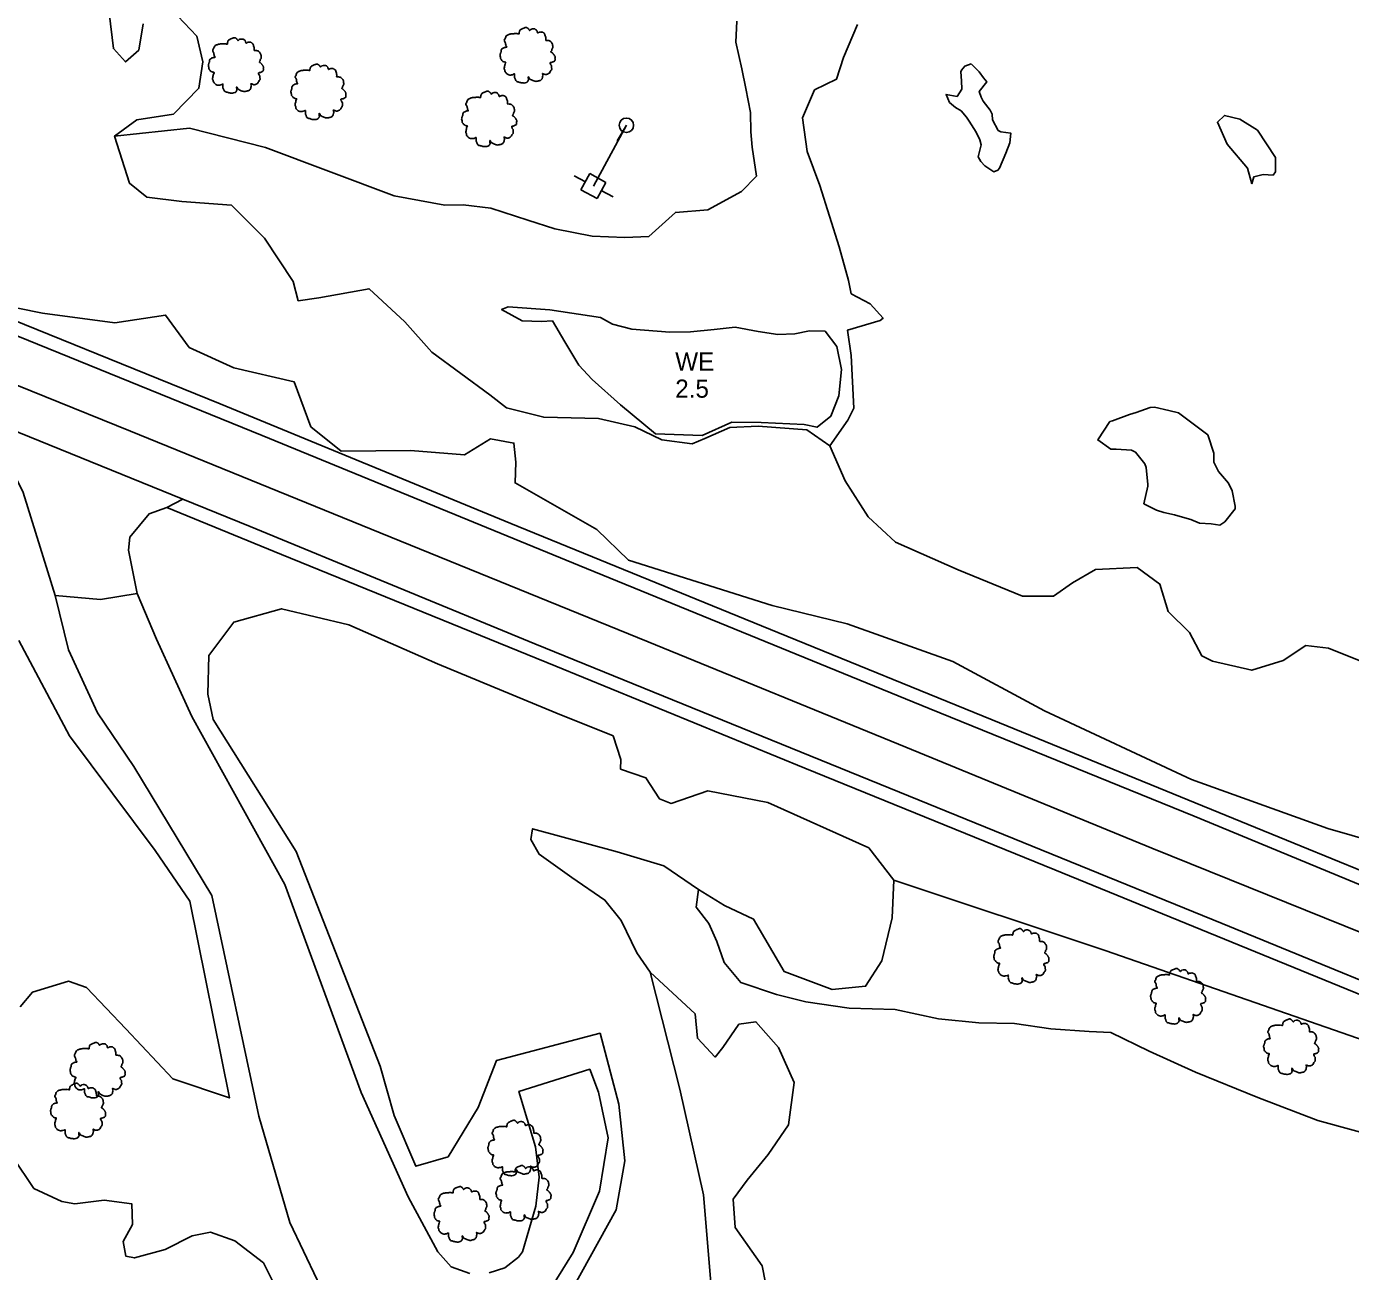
# Model space of a CAD drawing. Extents: x 2160437 to 2172832, y 205694 to 212444.
# Drawn here: x 2164307.9 to 2164673.6, y 209800.2 to 210144.2 of the extents above; entities that cross this region are included whole.
import ezdxf

# ---------------------------------------------------------------- set-up
doc = ezdxf.new("R2010")
doc.units = 0
for name, color, linetype in [('RD_EX_Driveway', 7, 'Continuous'), ('RD_EX_H2O_Pond', 7, 'Continuous'), ('RD_EX_H2O_txCode', 7, 'Continuous'), ('RD_EX_LaneStripe', 7, 'Continuous'), ('RD_EX_Road', 7, 'Continuous'), ('RD_EX_UT', 7, 'Continuous'), ('RD_EX_UT_Guy', 7, 'Continuous'), ('RD_EX_VEG', 7, 'Continuous'), ('RD_EX_VEG_ShrubLine', 7, 'Continuous'), ('RD_EX_VEG_TreeLine', 7, 'Continuous')]:
    doc.layers.add(name, color=color, linetype=linetype)

# ---------------------------------------------------------------- blocks, each defined once
blk = doc.blocks.new('T2')
at = {"layer": 'RD_EX_VEG'}
for points in [[(0.05, 7.21), (-0.25, 7.24), (-0.57, 7.14), (-0.82, 7.04), (-1.05, 6.96), (-1.27, 6.86), (-1.57, 6.69), (-1.8, 6.49), (-1.92, 6.24), (-1.97, 6.01), (-2.02, 5.74), (-2.02, 5.56), (-2.15, 5.54), (-2.3, 5.56), (-2.55, 5.64), (-2.8, 5.64), (-3.05, 5.64), (-3.4, 5.61), (-3.75, 5.61), (-4.02, 5.56), (-4.35, 5.51), (-4.72, 5.39), (-5.07, 5.26), (-5.37, 5.01), (-5.62, 4.54), (-5.75, 4.19), (-5.9, 3.94), (-5.75, 3.49), (-5.57, 3.14), (-5.55, 2.94), (-5.47, 2.52), (-5.37, 2.29), (-5.25, 2.09), (-5.32, 2.07), (-5.7, 2.02), (-6, 1.92), (-6.42, 1.69), (-6.64, 1.47), (-6.74, 1.14), (-6.77, 0.79), (-6.87, 0.59), (-6.94, 0.32), (-6.97, 0.24), (-7.02, -0.08), (-6.92, -0.53), (-6.89, -0.88), (-6.77, -1.11), (-6.62, -1.28), (-6.44, -1.53), (-6.05, -1.76), (-5.72, -1.86), (-5.52, -1.88), (-5.7, -2.38), (-5.75, -2.73), (-5.87, -3.13), (-5.87, -3.21), (-5.92, -3.68), (-5.77, -4.01), (-5.7, -4.38), (-5.52, -4.61), (-5.25, -4.91), (-4.92, -5.13), (-4.42, -5.26), (-4.02, -5.23), (-3.45, -5.06), (-3.2, -4.98), (-3.22, -5.16), (-3.2, -5.53), (-3.2, -5.96), (-3.05, -6.28), (-2.95, -6.56), (-2.8, -6.81), (-2.47, -7.03), (-2.07, -7.11), (-1.65, -7.26), (-1.2, -7.33), (-0.7, -7.36), (-0.1, -7.21), (0.18, -7.08), (0.28, -6.91), (0.48, -6.53), (0.43, -6.31), (0.45, -5.71), (0.55, -5.88), (0.73, -6.23), (1.23, -6.53), (1.63, -6.71), (2.1, -6.86), (2.4, -6.93), (2.88, -6.86), (3.25, -6.78), (3.63, -6.66), (3.93, -6.38), (4.1, -6.11), (4.15, -5.83), (4.23, -5.46), (4.28, -5.28)], [(4.28, -5.28), (4.2, -5.11), (4.15, -4.86), (4.23, -4.88), (4.4, -4.93), (4.68, -5.06), (4.9, -5.13), (5.23, -5.11), (5.5, -5.01), (5.95, -4.73), (6.22, -4.26), (6.5, -3.86), (6.57, -3.53), (6.52, -3.31), (6.5, -2.81), (6.3, -2.56), (6.25, -2.43), (6.15, -2.03), (6.22, -1.98), (6.5, -1.93), (6.87, -1.81), (7.15, -1.68), (7.37, -1.51), (7.45, -1.28), (7.42, -0.88), (7.47, -0.48), (7.4, -0.33), (7.3, -0.18), (7.22, 0.02), (7.07, 0.17), (6.97, 0.32), (6.87, 0.42), (6.75, 0.57), (6.57, 0.69), (6.42, 0.74), (6.37, 0.89), (6.52, 1.09), (6.57, 1.19), (6.6, 1.42), (6.82, 1.77), (6.87, 2.17), (6.82, 2.59), (6.77, 2.87), (6.62, 3.14), (6.42, 3.39), (6.3, 3.56), (6.12, 3.69), (5.8, 3.81), (5.55, 3.86), (5.2, 3.86), (5, 3.91), (5.03, 3.96), (5.03, 4.11), (5.03, 4.39), (4.95, 4.84), (4.8, 5.34), (4.8, 5.36), (4.7, 5.61), (4.48, 5.81), (4.3, 5.91), (4.1, 6.04), (3.85, 6.06), (3.55, 6.06), (3.28, 6.01), (3.08, 5.91), (2.9, 5.79), (2.83, 5.94), (2.73, 6.24), (2.68, 6.39), (2.53, 6.56), (2.3, 6.76), (1.85, 6.89), (1.23, 6.81), (0.93, 6.61), (0.78, 6.44), (0.73, 6.56), (0.53, 6.76), (0.43, 6.94), (0.25, 7.06), (0.1, 7.16), (0, 7.21)]]:
    blk.add_spline(points, degree=3, dxfattribs=at)
blk = doc.blocks.new('PP')
at = {"layer": 'RD_EX_UT'}
for p, q in [((2.49, 2.51), (-2.51, 2.51)), ((-2.51, 2.51), (-2.51, -2.49)), ((2.49, -2.49), (2.49, 2.51)), ((-5.94, -0.05), (-2.47, -0.05)), ((-2.51, -2.49), (2.49, -2.49)), ((2.42, -0.05), (6.06, -0.05))]:
    blk.add_line(p, q, dxfattribs=at)

msp = doc.modelspace()

# ---------------------------------------------------------------- linework, layer by layer
at = {"layer": 'RD_EX_Driveway'}
for points in [[(2164297.36, 210035.43), (2164299.48, 210030.49), (2164306.96, 210015.4), (2164313.81, 209993.51), (2164315.79, 209986.93), (2164328.32, 209985.83), (2164338.5, 209987.53), (2164336.08, 209999.47), (2164336.49, 210003.07), (2164341.75, 210009.48), (2164346.67, 210011.3), (2164351.12, 210013.61)], [(2164430.33, 209799.61), (2164425.17, 209801.5), (2164421.56, 209805.63), (2164413.34, 209820.81), (2164400.39, 209849.62), (2164379.25, 209907.1), (2164353.61, 209953.56), (2164343.81, 209974.91), (2164338.5, 209987.53)], [(2164315.79, 209986.93), (2164319.5, 209971.9), (2164327.56, 209954.54), (2164337.59, 209939.71), (2164359.06, 209904.07), (2164372.1, 209843.07), (2164380.65, 209813.71), (2164395.79, 209782.09), (2164405.35, 209768.14), (2164413.38, 209755.95)], [(2164451.52, 209793.58), (2164458.96, 209805.44), (2164466.18, 209822.43), (2164468.55, 209837.15), (2164465.89, 209849.74), (2164463.5, 209856.08), (2164443.91, 209849.94), (2164448.53, 209834.62), (2164449.48, 209826.28), (2164448.61, 209818.27), (2164444.9, 209805.65), (2164443.77, 209804.18), (2164440, 209801.24), (2164435.67, 209799.87)]]:
    msp.add_lwpolyline(points, dxfattribs=at)
at = {"layer": 'RD_EX_H2O_Pond'}
msp.add_lwpolyline([(2164503.69, 210061.09), (2164510.04, 210059.88), (2164515.48, 210059.01), (2164520.13, 210059.22), (2164524.16, 210060.06), (2164528.5, 210059.98), (2164531.76, 210055.71), (2164533.02, 210049.39), (2164532.33, 210042.07), (2164530.13, 210036.46), (2164526.31, 210033.42), (2164522.75, 210034.17), (2164510.83, 210034.75), (2164502.76, 210034.81), (2164494.51, 210031.11), (2164481.66, 210031.63), (2164471.99, 210039.66), (2164464.2, 210046.67), (2164460.48, 210050.55), (2164456.64, 210057.01), (2164453.19, 210062.86), (2164450.16, 210062.66), (2164444.83, 210062.81), (2164439.15, 210065.95), (2164440.93, 210066.71), (2164452.44, 210065.89), (2164466.42, 210063.74), (2164469.79, 210061.88), (2164475.14, 210060.57), (2164485.62, 210059.73), (2164491.31, 210059.83), (2164497.83, 210060.47)], close=True, dxfattribs=at)
at = {"layer": 'RD_EX_LaneStripe'}
msp.add_lwpolyline([(2164053.38, 210147.25), (2164123.11, 210119.29), (2164196.85, 210089.22), (2164265.56, 210061.12), (2164336.65, 210032.35), (2164405.58, 210004.27), (2164479.64, 209974.11), (2164550.79, 209945.02), (2164618.79, 209917.14), (2164687.93, 209889.27), (2164713.96, 209878.5)], dxfattribs=at)
at = {"layer": 'RD_EX_Road'}
for points in [[(2164719.32, 209893.53), (2164711.43, 209896.75), (2164660.02, 209917.67), (2164574.62, 209952.59), (2164515.44, 209976.77), (2164441.71, 210006.87), (2164361.41, 210039.86), (2164286.82, 210070.11), (2164199.81, 210105.86), (2164140.4, 210129.54), (2164103.67, 210144.43), (2164088.45, 210150.38), (2164055.87, 210164.02)], [(2164054.87, 210160.36), (2164149.67, 210121.83), (2164199.63, 210101.52), (2164285.68, 210066.64), (2164373.04, 210031.13), (2164462.58, 209994.39), (2164557.26, 209955.73), (2164630.42, 209925.95), (2164717.47, 209890.02)], [(2164708.26, 209867.65), (2164638.19, 209896.35), (2164549.03, 209932.58), (2164448.32, 209973.61), (2164369.65, 210006), (2164351.12, 210013.61), (2164297.36, 210035.43), (2164218.93, 210067.29), (2164124.14, 210105.98), (2164049.4, 210135.92)], [(2164346.67, 210011.3), (2164378.36, 209998.3), (2164454.1, 209967.4), (2164522.93, 209939.22), (2164591.97, 209911.12), (2164706.89, 209864.18)]]:
    msp.add_lwpolyline(points, dxfattribs=at)
at = {"layer": 'RD_EX_UT'}
msp.add_line((2164473.62, 210116.86), (2164471.04, 210112.58), dxfattribs=at)
msp.add_circle((2164473.62, 210116.86), 2, dxfattribs=at)
at = {"layer": 'RD_EX_UT_Guy'}
msp.add_lwpolyline([(2164473.62, 210116.86), (2164464.52, 210100.06)], dxfattribs=at)
at = {"layer": 'RD_EX_VEG_ShrubLine'}
for points in [[(2164504.1, 210145.59), (2164503.86, 210139.81), (2164505.54, 210132.41), (2164506.61, 210127.01), (2164507.86, 210120.4), (2164508, 210115.05), (2164508.33, 210110.83), (2164509.54, 210102.79), (2164505.44, 210098.56), (2164496.15, 210093.47), (2164487.15, 210092.8), (2164479.8, 210086.13), (2164473.21, 210085.88), (2164464.19, 210086.25), (2164453.81, 210088.24), (2164446.35, 210090.61), (2164436.14, 210093.96), (2164428.52, 210094.9), (2164423.5, 210094.8), (2164409.48, 210097.4), (2164373.97, 210110.71), (2164352.9, 210116.04), (2164332.25, 210113.85)], [(2164529.77, 210028.32), (2164534.74, 210035.35), (2164536.43, 210038.73), (2164535.69, 210053.22), (2164534.67, 210060.21), (2164543.69, 210062.96), (2164544.5, 210063.56), (2164540.92, 210067.5), (2164535.69, 210070.31), (2164534.97, 210073.93), (2164532.35, 210083.26), (2164527.02, 210100.21), (2164523.59, 210109.6), (2164522.22, 210118.91), (2164525.61, 210126.64), (2164531.66, 210129.58), (2164533.6, 210135.55), (2164537.44, 210144.69)], [(2164652.96, 210107.93), (2164647.99, 210115.49), (2164643.05, 210118.53), (2164638.84, 210119.57), (2164636.86, 210117.69), (2164639.58, 210111.68), (2164645.22, 210104.97), (2164646.37, 210100.68)], [(2164652.96, 210107.93), (2164652.89, 210104), (2164652.23, 210103.07), (2164649.53, 210103.25), (2164646.93, 210102.61), (2164646.37, 210100.68)], [(2164547.51, 209908.34), (2164605.91, 209888.89), (2164706.09, 209854.04)], [(2164684.14, 209836.59), (2164664.61, 209841.89), (2164648.07, 209848.25), (2164630.86, 209855.26), (2164618.03, 209861.05), (2164607.45, 209866.25), (2164601.45, 209866.52), (2164590.9, 209867.21), (2164580.85, 209868.75), (2164570.96, 209868.91), (2164559.85, 209869.96), (2164547.82, 209872.57), (2164535.15, 209872.94), (2164523.17, 209874.74), (2164515.06, 209876.74), (2164505.19, 209880.01), (2164500.63, 209885.52), (2164498.63, 209891.39), (2164496.4, 209896.35), (2164492.89, 209900.85), (2164493.58, 209905.76)], [(2164480.19, 209882.88), (2164492.57, 209871.38), (2164493.23, 209864.66), (2164498.1, 209859.43), (2164500.29, 209862.05), (2164504.69, 209868.55), (2164509.41, 209869.2), (2164515.64, 209862.04), (2164519.92, 209852.4), (2164518.42, 209840.71), (2164512.77, 209832.49), (2164507, 209825.47), (2164503.07, 209820.14), (2164503.68, 209812.37), (2164511.11, 209801.74), (2164512.03, 209797.07), (2164507.67, 209793.07), (2164504.25, 209788.78), (2164502.79, 209782.53), (2164503.01, 209770.38), (2164498.61, 209752.18)]]:
    msp.add_lwpolyline(points, dxfattribs=at)
for points in [[(2164568.86, 210133.79), (2164567.06, 210133.18), (2164566.15, 210132.09), (2164566, 210131.62), (2164566.21, 210129.12), (2164566.26, 210126.82), (2164566.26, 210126.82), (2164564.98, 210124.81), (2164561.92, 210125.37), (2164562.87, 210123.18), (2164564.51, 210121.81), (2164566.11, 210120.83), (2164567.57, 210119.13), (2164568.33, 210117.95), (2164570.25, 210114.99), (2164571.28, 210112.79), (2164571.63, 210111.41), (2164570.77, 210108.16), (2164571.49, 210106.88), (2164572.67, 210105.61), (2164575.11, 210104.04), (2164576.25, 210104.43), (2164576.68, 210105.05), (2164578.43, 210109.19), (2164579.57, 210112.01), (2164579.77, 210114.68), (2164577.01, 210115.01), (2164576.3, 210115.44), (2164574.78, 210118.34), (2164574.69, 210119.97), (2164574.12, 210121.04), (2164572.16, 210123.56), (2164571.57, 210124.6), (2164571.1, 210126.23), (2164573.17, 210128.87), (2164572.28, 210129.96), (2164572.28, 210129.96), (2164571.06, 210131.58)], [(2164616.52, 210012.24), (2164620.05, 210010.49), (2164622.04, 210009.84), (2164625.01, 210009.23), (2164627.2, 210008.62), (2164629.53, 210007.94), (2164631.91, 210006.94), (2164635.18, 210006.74), (2164637.5, 210006.42), (2164638.93, 210007.34), (2164641.76, 210010.88), (2164641.78, 210011.59), (2164640.98, 210015.85), (2164639.98, 210018.03), (2164637.14, 210021.22), (2164635.85, 210023.83), (2164635.91, 210026.27), (2164634.27, 210031.32), (2164634.27, 210031.32), (2164629.04, 210035.21), (2164626.17, 210037.39), (2164623.42, 210038.07), (2164619.46, 210039), (2164618.29, 210038.93), (2164614.42, 210037.53), (2164612.59, 210036.91), (2164607.91, 210035.16), (2164607.18, 210035), (2164603.84, 210029.95), (2164607.42, 210027.34), (2164608.89, 210027.4), (2164613.14, 210027.13), (2164614.22, 210026.58), (2164616.86, 210023.37), (2164617.16, 210022.27), (2164617.61, 210017.64), (2164617.68, 210017.12)]]:
    msp.add_lwpolyline(points, close=True, dxfattribs=at)
at = {"layer": 'RD_EX_VEG_TreeLine'}
for points in [[(2164330.72, 210147.94), (2164331.94, 210138.04), (2164335.27, 210134.34), (2164338.9, 210137.64), (2164340.1, 210144.9)], [(2164349.69, 210147.04), (2164354.96, 210141.51), (2164356.6, 210134.42), (2164355.54, 210127.09), (2164348.5, 210119.92), (2164338.37, 210118.32), (2164332.25, 210113.85), (2164336.35, 210100.86), (2164341.15, 210096.98), (2164350.84, 210095.84), (2164364.52, 210094.77), (2164373.61, 210085.69), (2164381.59, 210073.73), (2164382.98, 210068.37), (2164388.63, 210069.21), (2164402.52, 210071.71), (2164412.41, 210062.56), (2164419.84, 210054.2), (2164435.89, 210042.43), (2164440.51, 210038.81), (2164450.8, 210036.2), (2164465.92, 210035.81), (2164475.95, 210033.55), (2164483.4, 210029.93), (2164491.78, 210028.83), (2164495.27, 210030.33), (2164502.2, 210033.36), (2164510.06, 210033.76), (2164523.44, 210032.71), (2164529.77, 210028.32), (2164534.02, 210018.63), (2164540.42, 210008.64), (2164547.91, 210001.64), (2164565.27, 209994.01), (2164583.04, 209986.8), (2164591.63, 209986.81), (2164596.89, 209990.41), (2164603.17, 209994.14), (2164614.67, 209994.65), (2164620.98, 209990.1), (2164623.3, 209982.52), (2164629.12, 209976.75), (2164632.6, 209970.28), (2164635.55, 209968.84), (2164635.55, 209968.84), (2164646.36, 209966.3), (2164655.01, 209969.04), (2164661.28, 209973.14), (2164667.59, 209972.36), (2164676.06, 209969.01)], [(2164694.93, 209914.64), (2164667.39, 209922.55), (2164629.71, 209936.11), (2164589.15, 209955.05), (2164563.78, 209968.76), (2164534.58, 209979.15), (2164513.84, 209984.15), (2164474.2, 209996.75), (2164465.44, 210005.22), (2164442.86, 210018.05), (2164443.09, 210023.82), (2164442.54, 210029.05), (2164436.04, 210030.21), (2164428.91, 210025.77), (2164413.97, 210026.98), (2164394.87, 210026.8), (2164386.43, 210033.56), (2164381.84, 210045.99), (2164365.19, 210049.82), (2164352.85, 210055.5), (2164346.33, 210064.41), (2164332.32, 210062.32), (2164312.34, 210064.99), (2164286.82, 210070.11)], [(2164359.51, 209952.69), (2164357.99, 209959.67), (2164358.23, 209970.39), (2164365.14, 209979.55), (2164378.39, 209983.3), (2164396.97, 209978.85), (2164421.48, 209968.03), (2164454.15, 209954.54), (2164469.96, 209948.15), (2164472.11, 209941.67), (2164472, 209939.02), (2164479, 209936.56), (2164482.77, 209930.74), (2164485.98, 209929.49), (2164496.11, 209932.95), (2164512.7, 209929.8), (2164540.57, 209917.25), (2164547.51, 209908.34), (2164547.04, 209897.87), (2164544.15, 209886.02), (2164539.71, 209879.01), (2164530.5, 209878.14), (2164517.16, 209883.07), (2164508.75, 209897.56), (2164500.69, 209901.27), (2164493.58, 209905.76), (2164483.92, 209912.23), (2164471.08, 209916.1), (2164447.72, 209922.5), (2164447.26, 209919.59), (2164449.55, 209915.45), (2164458.59, 209909.08), (2164467.67, 209902.81), (2164472.18, 209897.19), (2164476.5, 209888.19), (2164480.19, 209882.88), (2164488.39, 209850.56), (2164494.92, 209821.37), (2164498.53, 209778.37)], [(2164305.76, 209974.54), (2164319.79, 209948.19), (2164343.46, 209916.52), (2164353.04, 209902.47), (2164363.97, 209848.14), (2164348.35, 209853.43), (2164335.33, 209867.27), (2164324.45, 209878.66), (2164319.55, 209880.43), (2164309.53, 209877.34), (2164306.13, 209873.34)], [(2164405.59, 209856.94), (2164382.41, 209916.25), (2164359.51, 209952.69)], [(2164458.83, 209795.6), (2164470.81, 209817.22), (2164473.2, 209830.76), (2164471.56, 209846.42), (2164466.34, 209866.04), (2164437.78, 209858.53), (2164432.7, 209845.52), (2164424.38, 209831.84), (2164415.44, 209829.29), (2164409.44, 209843.27), (2164405.59, 209856.94)], [(2164304.16, 209831.81), (2164309.96, 209823.17), (2164317.69, 209819.54), (2164321.25, 209818.91), (2164329.38, 209819.9), (2164337.02, 209818.89), (2164337.23, 209813.16), (2164334.61, 209808.51), (2164335.33, 209804.47), (2164337.73, 209803.94), (2164346.21, 209806.28), (2164353.65, 209810.04), (2164358.77, 209811.05), (2164365.5, 209808.65), (2164373.4, 209802.55), (2164378.1, 209793.19)]]:
    msp.add_lwpolyline(points, dxfattribs=at)

# ---------------------------------------------------------------- block references
at = {"layer": 'RD_EX_UT', "xscale": 1.0199999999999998, "yscale": 1.0199999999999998, "rotation": -28.687493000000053}
msp.add_blockref('PP', (2164464.52, 210100.06), dxfattribs=at)
at = {"layer": 'RD_EX_VEG', "xscale": 1.0499999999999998, "yscale": 1.0499999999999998}
for p in [(2164365.53, 210133.45), (2164446.09, 210136.26), (2164388.32, 210126.16), (2164435.48, 210118.68), (2164582.48, 209887.33), (2164625.79, 209876.3), (2164657.01, 209862.37), (2164327.32, 209855.88), (2164321.93, 209844.6), (2164442.74, 209834.38), (2164444.96, 209821.88), (2164427.85, 209816.07)]:
    msp.add_blockref('T2', p, dxfattribs=at)

# ---------------------------------------------------------------- texts
at = {"layer": 'RD_EX_H2O_txCode'}
for s, p in [('WE', (2164487.11, 210049.1)), ('2.5', (2164487.11, 210041.6))]:
    msp.add_text(s, height=5, dxfattribs=at).set_placement(p)

doc.saveas('drawing.dxf')
